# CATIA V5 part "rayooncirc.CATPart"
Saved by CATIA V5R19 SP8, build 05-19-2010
Part number: rayoon
Publications: "rayon_roue"
Bounding box of the stored display mesh (mm): x -406 to 0, y -203 to 203, z -1 to 28.021
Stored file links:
  G:\EU_thinkMotion\CFAO_2010\SIL_groupe1\SIL_groupe1\A reprendre\scador\monocycle\rayooncirc.CATPart
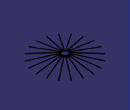
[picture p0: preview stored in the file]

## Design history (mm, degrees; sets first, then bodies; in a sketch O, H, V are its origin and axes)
Parameters
  rayon_roue = 200 mm
Set1
  Point1: type OnPlane, Support zx-plane, H 2, V 0, Direction (-1, 0, 0)
  Point2: (-203 {= -rayon_roue-3mm}, 0, 0)
  Line1: type Normal, RefPoint Point2, RefSkin xy-plane, Start 0, End 500
Body1 (main body)
  Sketch1 on yz-plane, origin (0, 0, 0), H (0, 1, 0), V (0, 0, 1)
    circle A1 centre (0, 0) radius 1
  Sketch2 on zx-plane, origin (0, 0, 0), H (-1, 0, 0), V (0, 0, 1)
    line L1 (0, 0) -> (180.4639, 27.0696)
    point P2 (180.8348, 24.5973)
    arc A1 centre (180.8348, 24.5973) radius 2.5 from (181.2057, 22.1249) to (180.4639, 27.0696) ccw
    line L2 (181.2057, 22.1249) -> (171.3163, 20.6415)
    angle L1 H = 171.4692 {= 180deg -atan(30mm/rayon_roue)}
    length L2 = 10
    distance P2 A1 = 2.5
    length L1 = 182.4829 {= sqrt((30mm)*(30mm)+(rayon_roue -20mm)*(rayon_roue -20mm))}
    tangency: A1 L1, L2 A1
    parallelism: L2 L1
  Rib1: profile Sketch1, centre curve Sketch2
  CircPattern1: of the body so far, instances 21, angular step 18, axis from Line1
Relations
  Sketch2.length(L1) = 1000*sqrt((0.03)*(0.03)+(rayon_roue /1000-0.03)*(rayon_roue /1000-0.03) (deactivated)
